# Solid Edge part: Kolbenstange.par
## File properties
Last saved by: ahadarics
Revision: 76
Dokumentum tartalom típus: 0
Sűrűség: 0,000 kg/m^3
Pontosság: 0,990
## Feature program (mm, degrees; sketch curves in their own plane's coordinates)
base feature "unnamed BaseFeature 1"
sketch for "unnamed Protrusion 1" plane through (46.75, 0, 0) normal (1, 0, 0) x-axis (0, 1, 0)
  circle centre (0, 0) radius 5
extrude "unnamed Protrusion 1" add finite 25.5 along -normal
thread "Menet_1"  ThreadDepth = 12 mm
chamfer "Letörés_1" setback 0.4
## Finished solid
Body 1: solid body, 7 faces, 6 edges, 0 vertices.
  Faces by surface: cylinder 3, plane 3, cone 1
  Edges by curve: circle 6
Bounding box of the edges (mm): 73.750 x 10.000 x 10.000, from (-27, -5, -5) to (46.75, 5, 5).
Cylindrical faces by radius (mm): R2 x2, R5 x1
Conical faces (half-angle, radius in mm at the cone's reference point): 45 deg R1.6 x1
Planar faces by outward normal: +x 1, -x 2
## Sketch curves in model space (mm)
circle centre (46.75, 0, 0) radius 5
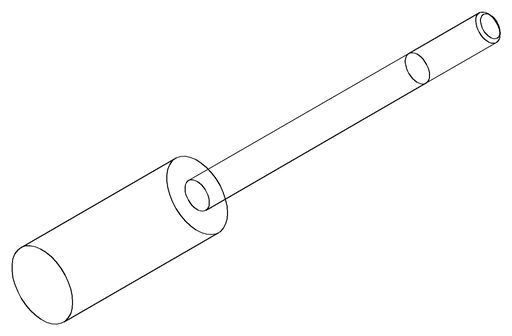
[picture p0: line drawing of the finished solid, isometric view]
